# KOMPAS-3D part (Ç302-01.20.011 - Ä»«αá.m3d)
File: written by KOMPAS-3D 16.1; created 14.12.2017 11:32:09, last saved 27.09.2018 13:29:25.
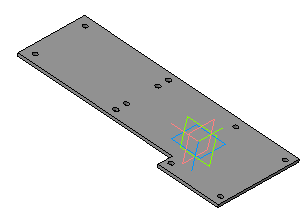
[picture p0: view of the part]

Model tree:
1. Эскиз:1
2. Листовое тело:1
     Расстояние 1 = 10; Расстояние 2 = 10; Радиус сгиба = 5
3. Сгиб:1
4. Сгиб(1) - Сгиб:1
     Радиус сгиба = 5; Коэффициент = 0.4; Величина сгиба = 10; Ширина освобождения сгиба = 3; Ширина сгиба = 104; Смещение сгиба = 2; Длина 2 = 10
5. Сгиб:2
6. Сгиб(1) - Сгиб:2
     Радиус сгиба = 5; Коэффициент = 0.4; Величина сгиба = 10; Ширина освобождения сгиба = 3; Ширина сгиба = 104; Смещение сгиба = 2; Отступ 2 = 266; Длина 2 = 10
7. Сгиб:3
8. Сгиб(1) - Сгиб:3
     Радиус сгиба = 5; Коэффициент = 0.4; Величина сгиба = 10; Толщина листового тела = 5; Ширина освобождения сгиба = 3; Ширина сгиба = 134; Смещение сгиба = 2; Длина 2 = 10
9. Сгиб:4
10. Сгиб(1) - Сгиб:4
     Радиус сгиба = 5; Коэффициент = 0.4; Величина сгиба = 10; Толщина листового тела = 5; Ширина освобождения сгиба = 3; Ширина сгиба = 104; Длина 1 = 30; Длина 2 = 10
11. Сгиб:5
12. Сгиб(1) - Сгиб:5
     Радиус сгиба = 5; Коэффициент = 0.4; Величина сгиба = 10; Толщина листового тела = 5; Ширина освобождения сгиба = 3; Ширина сгиба = 104; Длина 1 = 30; Длина 2 = 10
13. Сгиб:6
14. Сгиб(1) - Сгиб:6
     Радиус сгиба = 5; Коэффициент = 0.4; Величина сгиба = 10; Толщина листового тела = 5; Ширина освобождения сгиба = 3; Ширина сгиба = 134; Длина 1 = 30; Длина 2 = 10
15. Эскиз:8
16. Вырез в листовом теле:1  (labels: Полипропилен  ГОСТ 26996-86)
     Расстояние 1 = 10; Глубина выреза = 10

Expressions: 26+3; 250+16
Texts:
  Body Specification ( left align )
  Body Specificaton ( centered )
